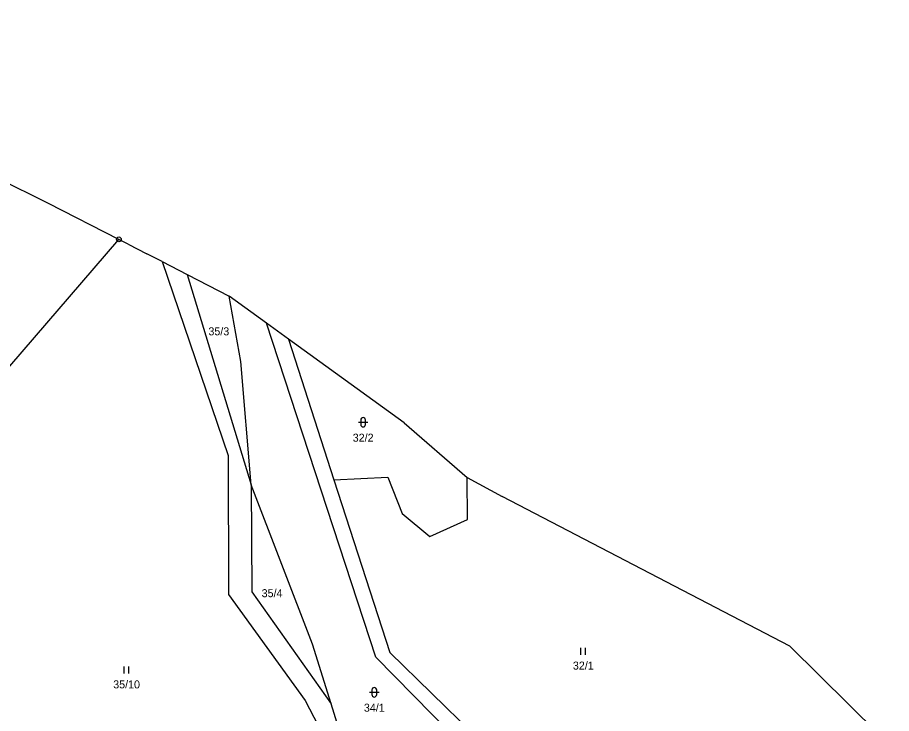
# Model space of a CAD drawing. Extents: x -601877 to -599786, y -1122905 to -1121218.
# Drawn here: x -600177.9 to -599992.2, y -1121690.7 to -1121542.8 of the extents above; entities that cross this region are included whole.
import ezdxf
from ezdxf.enums import TextEntityAlignment as Align

# ---------------------------------------------------------------- set-up
doc = ezdxf.new("R2010")
doc.units = 0
doc.header["$LTSCALE"] = 0.68
for name, color, linetype, lineweight in [('1', 7, 'Continuous', 25), ('3', 7, 'Continuous', 25), ('8', 7, 'Continuous', 25)]:
    doc.layers.add(name, color=color, linetype=linetype, lineweight=lineweight)
doc.layers.add('2', color=7, linetype='Continuous')

msp = doc.modelspace()

# ---------------------------------------------------------------- linework, layer by layer
at = {"layer": '1'}
for p, q in [((-600171.3, -1121582.36), (-600251.37, -1121542.84)), ((-600156.33, -1121589.98), (-600171.3, -1121582.36)), ((-600219.7, -1121663.67), (-600156.33, -1121589.98)), ((-600154.39, -1121590.97), (-600156.33, -1121589.98)), ((-600154.39, -1121590.97), (-600150.37, -1121593.04)), ((-600147.16, -1121594.7), (-600150.37, -1121593.04)), ((-600147.16, -1121594.7), (-600141.84, -1121597.44)), ((-600147.16, -1121594.7), (-600133.14, -1121635.92)), ((-600141.84, -1121597.44), (-600132.9, -1121602.04)), ((-600141.84, -1121597.44), (-600128.21, -1121642.16)), ((-600124.95, -1121607.81), (-600132.9, -1121602.04)), ((-600130.39, -1121615.93), (-600132.9, -1121602.04)), ((-600120.31, -1121611.17), (-600124.95, -1121607.81)), ((-600101.76, -1121678.76), (-600124.95, -1121607.81)), ((-600095.76, -1121628.95), (-600120.31, -1121611.17)), ((-600120.31, -1121611.17), (-600110.64, -1121641.11)), ((-600128.21, -1121642.16), (-600130.39, -1121615.93)), ((-600095.76, -1121628.95), (-600082.38, -1121640.6)), ((-600133.14, -1121635.92), (-600133.07, -1121665.44)), ((-600110.64, -1121641.11), (-600099.2, -1121640.51)), ((-600099.2, -1121640.51), (-600096.17, -1121648.22)), ((-600082.38, -1121640.6), (-600074.92, -1121644.62)), ((-600082.28, -1121649.54), (-600082.38, -1121640.6)), ((-600128.21, -1121642.16), (-600128.07, -1121664.86)), ((-600115.18, -1121676.01), (-600128.21, -1121642.16)), ((-600110.64, -1121641.11), (-600098.79, -1121677.77)), ((-600013.81, -1121676.4), (-600074.92, -1121644.62)), ((-600096.17, -1121648.22), (-600090.26, -1121653.15)), ((-600090.26, -1121653.15), (-600082.28, -1121649.54)), ((-600128.07, -1121664.86), (-600111.25, -1121688.66)), ((-600133.07, -1121665.44), (-600116.75, -1121687.93)), ((-600111.25, -1121688.66), (-600115.18, -1121676.01)), ((-600098.79, -1121677.77), (-600078.77, -1121697.25)), ((-600013.81, -1121676.4), (-599992.21, -1121697.77)), ((-600080.86, -1121700.01), (-600101.76, -1121678.76)), ((-600116.75, -1121687.93), (-600106.45, -1121707.88)), ((-600109.68, -1121693.73), (-600111.25, -1121688.66))]:
    msp.add_line(p, q, dxfattribs=at)
at = {"layer": '3'}
for p, q in [((-600105.451, -1121628.851), (-600103.449, -1121628.851)), ((-600104.951, -1121628.351), (-600104.951, -1121629.352)), ((-600103.949, -1121629.352), (-600103.949, -1121628.351)), ((-600058.191, -1121678.27), (-600058.191, -1121676.77)), ((-600057.19, -1121678.27), (-600057.19, -1121676.77)), ((-600155.201, -1121682.26), (-600155.201, -1121680.76)), ((-600154.2, -1121682.26), (-600154.2, -1121680.76)), ((-600103.071, -1121686.221), (-600101.069, -1121686.221)), ((-600102.571, -1121685.721), (-600102.571, -1121686.722)), ((-600101.569, -1121686.722), (-600101.569, -1121685.721))]:
    msp.add_line(p, q, dxfattribs=at)
for centre, start, end in [((-600104.45, -1121628.3509), 0, 180), ((-600104.45, -1121629.3509), 180, 359.98789), ((-600102.07, -1121685.7209), 0, 180), ((-600102.07, -1121686.7209), 180, 359.98789)]:
    msp.add_arc(centre, 0.5, start, end, dxfattribs=at)
at = {"layer": '8'}
for radius in [0.5, 0.0303]:
    msp.add_circle((-600156.33, -1121589.9799), radius, dxfattribs=at)

# ---------------------------------------------------------------- texts
at = {"layer": '2'}
for s, p in [('35/3', (-600135.099, -1121610.375)), ('32/2', (-600104.449, -1121632.975)), ('35/4', (-600123.789, -1121666.015)), ('32/1', (-600057.679, -1121681.395)), ('35/10', (-600154.69, -1121685.385)), ('34/1', (-600102.069, -1121690.345))]:
    msp.add_text(s, height=1.7, dxfattribs=at).set_placement(p, align=Align.CENTER)

doc.saveas('drawing.dxf')
